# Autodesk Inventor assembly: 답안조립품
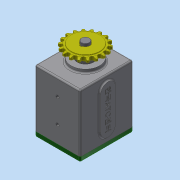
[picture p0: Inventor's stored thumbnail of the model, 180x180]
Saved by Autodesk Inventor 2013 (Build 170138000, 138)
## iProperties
Created: 2018-12
Part Number: 답안조립품
Document SubType Name: Assembly
Designer: dgall
Author: dgall
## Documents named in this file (16)
- C:\Users\dgall\Desktop\381207V1039\답안조립품.iam
- C:\Users\dgall\Desktop\381207V1039\본체.ipt
- C:\Users\dgall\Desktop\381207V1039\커버.ipt
- C:\Users\dgall\Desktop\381207V1039\베어링 608.ipt
- C:\Users\dgall\Desktop\381207V1039\서브 기어 축.ipt
- C:\Users\dgall\Desktop\381207V1039\메인 기어 축.ipt
- C:\Users\dgall\Desktop\381207V1039\베어링 6003.ipt
- C:\Users\dgall\Desktop\381207V1039\오일 실 8 22 7.ipt
- C:\Users\dgall\Desktop\381207V1039\오일 실 17 32 8.ipt
- C:\Users\dgall\Desktop\381207V1039\키 5 x 5 x 18.ipt
- C:\Users\dgall\Desktop\381207V1039\부시.ipt
- C:\Users\dgall\Desktop\381207V1039\슬라이더.ipt
- C:\Users\dgall\Desktop\381207V1039\가변스프링.ipt
- C:\Users\dgall\Desktop\381207V1039\스프로킷.ipt
- C:\Users\dgall\Desktop\381207V1039\멈춤나사 M3x8.ipt
- C:\Users\dgall\Desktop\381207V1039\볼트 M4 x 10.ipt
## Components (1 placed, 1 different names)
1. 가변스프링:1
